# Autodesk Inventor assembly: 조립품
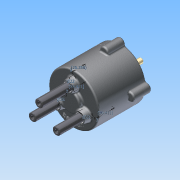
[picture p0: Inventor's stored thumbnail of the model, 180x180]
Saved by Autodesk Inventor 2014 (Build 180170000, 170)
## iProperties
Created: 2015-09
Part Number: 조립품
Document SubType Name: Assembly
Designer: study
Mass: 2160.14 g
Surface Area: 1801.25 cm^2
Volume: 438.509 cm^3
Density: 4.92611 g/cm^3
Author: study
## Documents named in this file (14)
- C:\Users\study\Desktop\350916V1008\조립품.iam
- C:\Users\study\Desktop\350916V1008\몸체.ipt
- C:\Users\study\Desktop\350916V1008\M5x0.8x20.ipt
- C:\Users\study\Desktop\350916V1008\오일실.ipt
- C:\Users\study\Desktop\350916V1008\커버.ipt
- C:\Users\study\Desktop\350916V1008\메인 축.ipt
- C:\Users\study\Desktop\350916V1008\판캠.ipt
- C:\Users\study\Desktop\350916V1008\멈춤링 22 x 1.2.ipt
- C:\Users\study\Desktop\350916V1008\베어링 NA 4900.ipt
- C:\Users\study\Desktop\350916V1008\멈춤링 10 x 1.ipt
- C:\Users\study\Desktop\350916V1008\슬라이드 축.ipt
- C:\Users\study\Desktop\350916V1008\가변 스프링-11.ipt
- C:\Users\study\Desktop\350916V1008\가변 스프링-12.ipt
- C:\Users\study\Desktop\350916V1008\가변 스프링-13.ipt
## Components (7 placed, 4 different names)
1. 가변 스프링-11:1
2. 가변 스프링-12:1
3. 가변 스프링-13:1
4. M5x0.8x20:1
5. M5x0.8x20:2
6. M5x0.8x20:3
7. M5x0.8x20:4
